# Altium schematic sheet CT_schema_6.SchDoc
size 277 x 170 mm
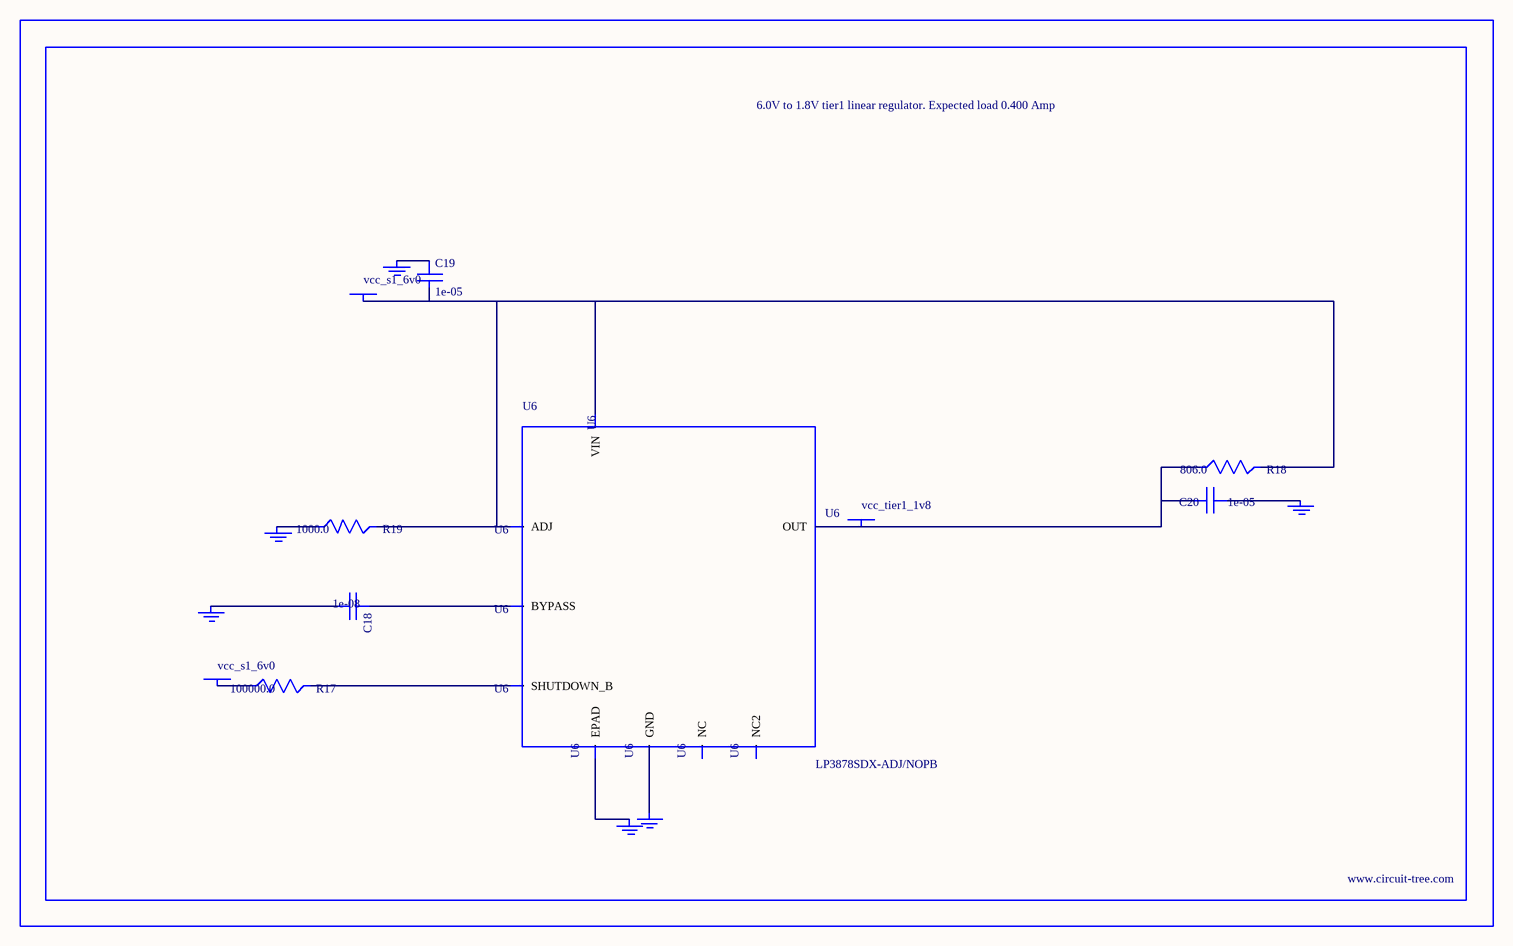
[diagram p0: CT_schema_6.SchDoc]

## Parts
BORDER5  (no value)
C18  1e-08  [C0402]
C19  1e-05  [C1206]
C20  1e-05  [C0805]
GND_INSTANCE_5_0  (no value)
GND_INSTANCE_5_1  (no value)
GND_INSTANCE_5_2  (no value)
GND_INSTANCE_5_3  (no value)
GND_INSTANCE_5_4  (no value)
GND_INSTANCE_5_5  (no value)
POWER_INSTANCE_5_0  vcc_s1_6v0
POWER_INSTANCE_5_1  vcc_s1_6v0
POWER_INSTANCE_5_2  vcc_tier1_1v8
R17  100000.0  [R0603]
R18  806.0  [R0603]
R19  1000.0  [R0603]
U6  LP3878SDX-ADJ/NOPB  [WSON-8]

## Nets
NetC18_1: C18.1 U6.1(BYPASS)
NetC18_2: C18.2 GND_INSTANCE_5_0.0(GND)
NetC19_1: C19.1 GND_INSTANCE_5_1.0(GND)
NetC19_2: C19.2 POWER_INSTANCE_5_0.0(PWR) R18.2 R19.2 U6.4(VIN) U6.6(ADJ)
NetC20_1: C20.1 GND_INSTANCE_5_2.0(GND)
NetC20_2: C20.2 POWER_INSTANCE_5_2.0(PWR) R18.1 U6.5(OUT)
NetGND_INSTANCE_5_3_0: GND_INSTANCE_5_3.0(GND) R19.1
NetGND_INSTANCE_5_4_0: GND_INSTANCE_5_4.0(GND) U6.PAD(EPAD)
NetGND_INSTANCE_5_5_0: GND_INSTANCE_5_5.0(GND) U6.3(GND)
NetPOWER_INSTANCE_5_1_0: POWER_INSTANCE_5_1.0(PWR) R17.1
NetR17_2: R17.2 U6.8(SHUTDOWN_B)

Not connected (* = marked no-connect by the designer): U6 2(NC) 7(NC2)

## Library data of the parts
BORDER5 = BORDER_PAGE5
C18 = C0402C103K3RAC
C19 = C1206C106K3RACTU
C20 = GRM219R60J106ME19D
GND_INSTANCE_5_0-GND_INSTANCE_5_5 = GND
POWER_INSTANCE_5_0-POWER_INSTANCE_5_2 = PWR
R17 = RC0603JR-07100KL
R18 = ERJ-3EKF8060V
R19 = RC0603JR-071KL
